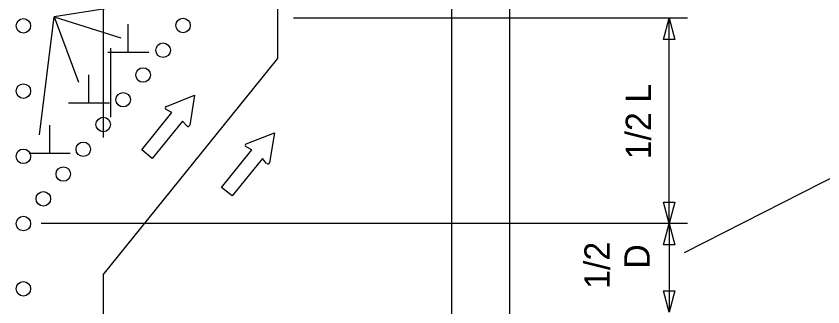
# Model space of a CAD drawing. Extents: x 16544 to 19504, y 5662 to 6909.
# Drawn here: x 16987.5 to 17209.8, y 6469.9 to 6550.1 of the extents above; entities that cross this region are included whole.
import ezdxf

# ---------------------------------------------------------------- set-up
doc = ezdxf.new("R2010")
doc.units = 0
for name, color, linetype in [('ALI_LEGAL_EX', 7, 'Continuous'), ('MT_SCRATCH_LEVEL_E', 7, 'Continuous'), ('PAVT_EDGE_EX', 7, 'Continuous'), ('TRAFFIC_SIGNS_PR', 7, 'Continuous'), ('TYPICAL_TEXT_DIMEN_PR', 7, 'Continuous')]:
    doc.layers.add(name, color=color, linetype=linetype)

msp = doc.modelspace()

# ---------------------------------------------------------------- linework, layer by layer
at = {"layer": 'ALI_LEGAL_EX'}
for points in [[(17013.46, 6541.23), (17013.46, 6522.22)], [(17013.46, 6541.23), (17013.46, 6524.21)]]:
    msp.add_lwpolyline(points, dxfattribs=at)
at = {"layer": 'MT_SCRATCH_LEVEL_E'}
for p, q in [((17028.87, 6525.2), (17036.64, 6528.24)), ((17028.87, 6525.2), (17036.64, 6528.24)), ((17036.64, 6528.24), (17035.3, 6520.02)), ((17036.64, 6528.24), (17035.3, 6520.02)), ((17030.39, 6523.5), (17028.81, 6524.37)), ((17030.39, 6523.5), (17028.81, 6524.37)), ((17022.08, 6513.17), (17030.39, 6523.5)), ((17022.08, 6513.17), (17030.39, 6523.5)), ((17033.31, 6521.15), (17024.99, 6510.82)), ((17033.31, 6521.15), (17024.99, 6510.82)), ((17034.49, 6519.79), (17033.31, 6521.15)), ((17034.49, 6519.79), (17033.31, 6521.15)), ((17050.89, 6514.87), (17058.66, 6517.91)), ((17050.89, 6514.87), (17058.66, 6517.91)), ((17058.66, 6517.91), (17057.32, 6509.69)), ((17058.66, 6517.91), (17057.32, 6509.69)), ((17024.99, 6510.82), (17022.08, 6513.17)), ((17024.99, 6510.82), (17022.08, 6513.17)), ((17044.1, 6502.84), (17052.41, 6513.17)), ((17044.1, 6502.84), (17052.41, 6513.17)), ((17052.41, 6513.17), (17050.83, 6514.04)), ((17052.41, 6513.17), (17050.83, 6514.04)), ((17055.33, 6510.82), (17047.01, 6500.5)), ((17055.33, 6510.82), (17047.01, 6500.5)), ((17056.51, 6509.46), (17055.33, 6510.82)), ((17056.51, 6509.46), (17055.33, 6510.82)), ((17047.01, 6500.5), (17044.1, 6502.84)), ((17047.01, 6500.5), (17044.1, 6502.84))]:
    msp.add_line(p, q, dxfattribs=at)
for centre, start, end in [((17029.04, 6524.77), 111.3861, 241.123), ((17029.04, 6524.77), 111.3861, 241.123), ((17034.84, 6520.1), 221.1954, 350.7344), ((17034.84, 6520.1), 221.1954, 350.7344), ((17051.06, 6514.44), 111.3861, 241.123), ((17051.06, 6514.44), 111.3861, 241.123), ((17056.86, 6509.77), 221.1954, 350.7344), ((17056.86, 6509.77), 221.1954, 350.7344)]:
    msp.add_arc(centre, 0.463, start, end, dxfattribs=at)
at = {"layer": 'PAVT_EDGE_EX'}
for p, q in [((17011.46, 6880.02), (17011.46, 6516.57)), ((17107.46, 6880.02), (17107.46, 6106.05)), ((17123.46, 6880.02), (17123.46, 6106.05)), ((17011.46, 6794.72), (17011.46, 6522.22)), ((17059.46, 6590.85), (17059.46, 6538.35)), ((17011.46, 6478.73), (17059.46, 6538.35)), ((17011.46, 6478.73), (17011.46, 6309.01))]:
    msp.add_line(p, q, dxfattribs=at)
at = {"layer": 'TRAFFIC_SIGNS_PR'}
for centre in [(16989.46, 6547.41), (16989.46, 6547.41), (16989.46, 6547.41), (17033.46, 6547.51), (17027.96, 6540.68), (17022.46, 6533.85), (16989.46, 6529.41), (17016.96, 6527.02), (17011.46, 6520.19), (17005.96, 6513.36), (16989.46, 6511.41), (17000.46, 6506.53), (16994.96, 6499.7), (16989.46, 6492.87), (16989.46, 6474.87)]:
    msp.add_circle(centre, 2, dxfattribs=at)
at = {"layer": 'TYPICAL_TEXT_DIMEN_PR'}
for p, q in [((17139.51, 6572.32), (16997.97, 6549.9)), ((16993.88, 6517.37), (16997.97, 6549.9)), ((16997.97, 6549.9), (17004.69, 6531.83)), ((16997.97, 6549.9), (17016.35, 6544.09)), ((17172.46, 6549.51), (17063.88, 6549.51)), ((17165.89, 6543.65), (17167.46, 6549.51)), ((17167.46, 6492.87), (17167.46, 6549.51)), ((17167.46, 6549.51), (17169.03, 6543.65)), ((17018.37, 6540.05), (17018.37, 6547.83)), ((17167.46, 6543.65), (17165.89, 6543.65)), ((17169.03, 6543.65), (17167.46, 6543.65)), ((17023.99, 6540.05), (17012.74, 6540.05)), ((17007.54, 6526.12), (17007.54, 6533.9)), ((17013.16, 6526.12), (17001.91, 6526.12)), ((16996.71, 6512.19), (16996.71, 6519.98)), ((17002.33, 6512.19), (16991.08, 6512.19)), ((17171.69, 6484.9), (17219.15, 6509.1)), ((17167.46, 6492.87), (17165.89, 6498.73)), ((17165.89, 6498.73), (17167.46, 6498.73)), ((17167.46, 6498.73), (17169.03, 6498.73)), ((17169.03, 6498.73), (17167.46, 6492.87)), ((17172.46, 6492.87), (16994.34, 6492.87)), ((17165.89, 6487.01), (17167.46, 6492.87)), ((17167.46, 6492.87), (17169.03, 6487.01)), ((17167.46, 6492.87), (17167.46, 6468.41)), ((17167.46, 6487.01), (17165.89, 6487.01)), ((17169.03, 6487.01), (17167.46, 6487.01)), ((17167.46, 6468.41), (17165.89, 6474.27)), ((17165.89, 6474.27), (17167.46, 6474.27)), ((17167.46, 6474.27), (17169.03, 6474.27)), ((17169.03, 6474.27), (17167.46, 6468.41))]:
    msp.add_line(p, q, dxfattribs=at)

# ---------------------------------------------------------------- texts
for s, p in [('1/2 L', (17162.46, 6510.57)), ('1/2', (17151.09, 6474.83)), ('D', (17162.09, 6480.4))]:
    msp.add_text(s, height=7, rotation=90, dxfattribs=at).set_placement(p)

doc.saveas('drawing.dxf')
